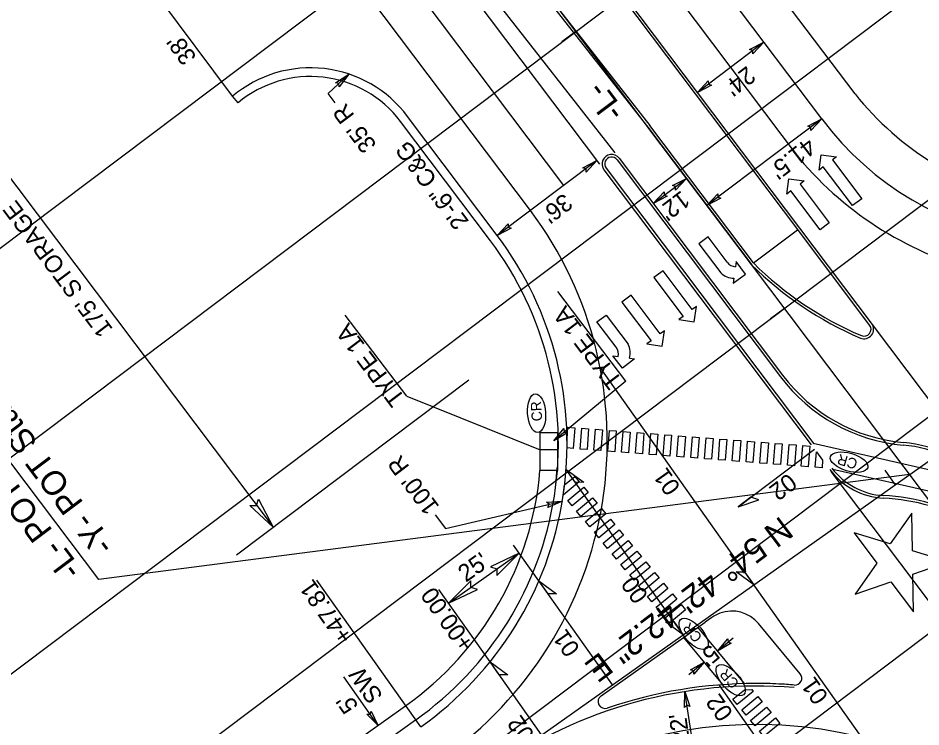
# Model space of a CAD drawing. Extents: x 1262309 to 1264352, y 775189 to 777755.
# Drawn here: x 1263122.7 to 1263383.2, y 776491.3 to 776695.9 of the extents above; entities that cross this region are included whole.
import ezdxf

# ---------------------------------------------------------------- set-up
doc = ezdxf.new("R2010")
doc.units = 0
for name, color, linetype in [('Default', 7, 'Continuous'), ('Old_Level_2', 7, 'Continuous'), ('Prop Conc 1ft 6in Curb and Gutter', 7, 'Continuous'), ('Prop Conc 2ft 6in Curb and Gutter', 7, 'Continuous'), ('Prop Conc 4in Sidewalk', 7, 'Continuous'), ('Prop Conc 5in Monolithic Keyed In Island', 7, 'Continuous'), ('Prop Conc 5in Monolithic Surface Mount Island', 7, 'Continuous'), ('Prop Dimension', 7, 'Continuous'), ('Prop Dimension Text', 7, 'Continuous'), ('Prop EOT', 7, 'Continuous'), ('Prop Horizontal Alignment', 7, 'Continuous'), ('Prop Horizontal Alignment Direction Label', 7, 'Continuous'), ('Prop Horizontal Alignment Station Label', 7, 'Continuous'), ('Prop Horizontal Alignment Tick Large', 7, 'Continuous'), ('Prop Horizontal Alignment Tick Small', 7, 'Continuous'), ('Prop Lane Arrow CELL', 7, 'Continuous'), ('Prop Lane Lines', 7, 'Continuous'), ('Prop Mkg Solid White Crosswalks', 7, 'Continuous'), ('Prop Paved Shoulder', 7, 'Continuous'), ('Prop RDY Traffic Signal CELL', 7, 'Continuous'), ('Prop Superelevation  Arrow CELL', 7, 'Continuous'), ('Prop Superelevation Label', 7, 'Continuous'), ('Prop Terminator CELL', 7, 'Continuous'), ('Scratch_Level_3', 7, 'Continuous')]:
    doc.layers.add(name, color=color, linetype=linetype)

msp = doc.modelspace()

# ---------------------------------------------------------------- linework, layer by layer
at = {"layer": 'Default'}
msp.add_line((1263283.6, 776691.99), (1263283.6, 776691.99), dxfattribs=at)
msp.add_line((1263283.6, 776691.99), (1263283.6, 776691.99), dxfattribs=at)
for centre, major_axis in [((1263272.29, 776581.88), (-0.35, 5.6)), ((1263362.45, 776567.74), (-5.38, 1.6)), ((1263317.6, 776518.17), (-3.75, 4.17)), ((1263328.26, 776504.81), (-3.75, 4.17))]:
    msp.add_ellipse(centre, major_axis=major_axis, ratio=0.462467, dxfattribs=at)
at = {"layer": 'Old_Level_2'}
for p, q in [((1263273.31, 776571.31), (1263273.32, 776576.31)), ((1263273.32, 776576.31), (1263278.32, 776576.3)), ((1263278.32, 776576.3), (1263278.31, 776571.3)), ((1263273.3, 776565.31), (1263273.31, 776571.31)), ((1263278.31, 776571.3), (1263273.31, 776571.31)), ((1263278.31, 776571.3), (1263278.3, 776565.3)), ((1263278.3, 776565.3), (1263273.3, 776565.31))]:
    msp.add_line(p, q, dxfattribs=at)
at = {"layer": 'Prop Conc 1ft 6in Curb and Gutter'}
for p, q in [((1263347.62, 776634.83), (1263140.59, 776909.69)), ((1263123.37, 776896.82), (1263304.93, 776664.85)), ((1263334.84, 776625.2), (1263304.93, 776664.85))]:
    msp.add_line(p, q, dxfattribs=at)
msp.add_arc((1263293.92, 776653.77), 2, 37.0029, 217.0037, dxfattribs=at)
at = {"layer": 'Prop Conc 2ft 6in Curb and Gutter'}
for p, q in [((1263186.18, 776671.42), (1263184.58, 776673.34)), ((1263258.96, 776631.62), (1263233.02, 776666.06)), ((1263218.79, 776480.21), (1263237.4, 776493.38))]:
    msp.add_line(p, q, dxfattribs=at)
for centre, radius, start, end in [((1263207.06, 776646.51), 32.5, 36.9874, 129.9598), ((1263181.08, 776572.96), 97.5, 305.2883, 36.9874)]:
    msp.add_arc(centre, radius, start, end, dxfattribs=at)
at = {"layer": 'Prop Conc 4in Sidewalk'}
for p, q in [((1263352.07, 776573.23), (1263401.96, 776561.79)), ((1263277.85, 776561.08), (1263278.2, 776566.07)), ((1263357.74, 776565.71), (1263408.37, 776554.17)), ((1263332.3, 776503.85), (1263318.84, 776520.08)), ((1263326.06, 776503.55), (1263314.74, 776517.18)), ((1263215.93, 776484.31), (1263234.51, 776497.46))]:
    msp.add_line(p, q, dxfattribs=at)
msp.add_arc((1263181.08, 776572.96), 92.5, 305.2883, 355.251, dxfattribs=at)
at = {"layer": 'Prop Conc 5in Monolithic Keyed In Island'}
for p, q in [((1263295.52, 776654.97), (1263342.67, 776592.37)), ((1263292.32, 776652.57), (1263352.25, 776573)), ((1263334.84, 776625.2), (1263347.59, 776634.81)), ((1263368.37, 776607.28), (1263347.62, 776634.83)), ((1263322.87, 776522.94), (1263320.88, 776521.53)), ((1263290.88, 776500.29), (1263320.88, 776521.53)), ((1263348.34, 776506.7), (1263336.34, 776521.16))]:
    msp.add_line(p, q, dxfattribs=at)
for centre, radius, start, end in [((1263405.23, 776696.15), 99.94, 225.2272, 246.8818), ((1263366.77, 776606.08), 2, 246.8818, 36.9866), ((1263382.61, 776622.45), 50, 216.9874, 264.7486), ((1263374.37, 776532.83), 40, 46.384, 84.7486), ((1263373.47, 776578.07), 20, 216.9874, 266.8533), ((1263368.91, 776495.2), 63, 36.9874, 86.8533), ((1263328.65, 776514.77), 10, 110.1849, 125.2883), ((1263328.65, 776514.77), 10, 39.6905, 110.1849), ((1263346.8, 776505.43), 2, 265.2295, 39.6905), ((1263335.59, 776371.14), 132.75, 90.0327, 108.8618), ((1263335.59, 776371.14), 132.75, 87.1691, 90.0327), ((1263335.59, 776371.14), 132.75, 85.2295, 87.1691), ((1263292.03, 776498.66), 2, 125.2883, 288.8618)]:
    msp.add_arc(centre, radius, start, end, dxfattribs=at)
at = {"layer": 'Prop Conc 5in Monolithic Surface Mount Island'}
msp.add_line((1263292.72, 776655.37), (1263292.72, 776655.37), dxfattribs=at)
at = {"layer": 'Prop Dimension'}
for p, q in [((1263091.05, 776688.64), (1263196.28, 776548.94)), ((1263212.13, 776674.14), (1263218.15, 776679.67)), ((1263214.19, 776671.4), (1263212.13, 776674.14)), ((1263354.56, 776666.75), (1263321.41, 776641.78)), ((1263289.71, 776654.79), (1263260.95, 776633.13)), ((1263234.82, 776586.76), (1263217.1, 776610.16)), ((1263185.76, 776541.02), (1263252.78, 776591.5)), ((1263234.82, 776586.76), (1263273.31, 776571.31)), ((1263246.05, 776548.59), (1263279.72, 776556.52)), ((1263243.04, 776552.58), (1263246.05, 776548.59)), ((1263272.95, 776533.48), (1263265.64, 776543.82)), ((1263246.89, 776527.03), (1263267.3, 776541.47)), ((1263258.86, 776510.12), (1263244.06, 776531.03)), ((1263328.97, 776516.96), (1263324.5, 776513.25)), ((1263320.66, 776510.06), (1263316.18, 776506.34)), ((1263318.43, 776479.93), (1263315.02, 776501.53))]:
    msp.add_line(p, q, dxfattribs=at)
at = {"layer": 'Prop Dimension Text'}
for p, q in [((1263337.8, 776688.92), (1263328.25, 776681.65)), ((1263328.25, 776681.65), (1263318.7, 776674.39)), ((1263305.92, 776642.4), (1263315.51, 776649.62)), ((1263298.01, 776591.1), (1263278.44, 776616.97)), ((1263298.01, 776591.1), (1263277.25, 776573.87)), ((1263238.85, 776491.34), (1263208.89, 776533.66)), ((1263226.53, 776491.81), (1263216.65, 776505.78))]:
    msp.add_line(p, q, dxfattribs=at)
for points in [[(1263333.75, 776686.81), (1263337.8, 776688.92), (1263334.69, 776685.54), (1263334.66, 776686.53)], [(1263322.75, 776676.5), (1263318.7, 776674.39), (1263321.82, 776677.77), (1263321.85, 776676.78)], [(1263285.66, 776652.68), (1263289.71, 776654.79), (1263286.59, 776651.41), (1263286.57, 776652.4)], [(1263265, 776635.24), (1263260.95, 776633.13), (1263264.07, 776636.5), (1263264.1, 776635.52)], [(1263281.18, 776576.18), (1263277.25, 776573.87), (1263280.19, 776577.4), (1263280.26, 776576.42)], [(1263192.1, 776557.06), (1263196.28, 776548.94), (1263189.56, 776555.21), (1263191.53, 776555.25)], [(1263260.85, 776535), (1263267.3, 776541.47), (1263258.99, 776537.55), (1263260.85, 776536.91)], [(1263253.35, 776533.49), (1263246.89, 776527.03), (1263255.21, 776530.95), (1263253.34, 776531.59)]]:
    msp.add_lwpolyline(points, close=True, dxfattribs=at)
at = {"layer": 'Prop EOT'}
for p, q in [((1263354.56, 776666.75), (1263027.28, 777101.26)), ((1263369.15, 776607.49), (1263141.16, 776910.18)), ((1263122.79, 776896.34), (1263304.34, 776664.39)), ((1263184.58, 776673.34), (1263162.01, 776703.54)), ((1263260.95, 776633.13), (1263235.06, 776667.5)), ((1263334.27, 776624.72), (1263304.34, 776664.39)), ((1263304.34, 776664.39), (1263334.27, 776624.72)), ((1263296.12, 776655.42), (1263343.27, 776592.82)), ((1263291.72, 776652.11), (1263351.48, 776572.78))]:
    msp.add_line(p, q, dxfattribs=at)
for centre, radius, start, end in [((1263207.06, 776646.51), 35, 36.8507, 129.9598), ((1263426.45, 776720.9), 90, 216.9873, 305.2883), ((1263293.92, 776653.77), 2.75, 36.9549, 216.9881), ((1263181.08, 776572.96), 100, 305.2883, 36.9874), ((1263405.23, 776696.15), 100.69, 225.2272, 246.8818), ((1263366.77, 776606.08), 2.75, 246.8818, 36.9866), ((1263382.61, 776622.45), 49.25, 216.9874, 264.7486), ((1263374.37, 776532.83), 40.75, 45.4749, 84.7486), ((1263373.47, 776578.07), 20.75, 216.9874, 266.8533), ((1263368.91, 776495.2), 62.25, 36.9874, 86.8533)]:
    msp.add_arc(centre, radius, start, end, dxfattribs=at)
at = {"layer": 'Prop Horizontal Alignment'}
for p, q in [((1263334.24, 776624.75), (1263127.22, 776899.61)), ((1263049.28, 776330.22), (1263743.09, 776821.26)), ((1263830.93, 775965.32), (1263334.24, 776624.75))]:
    msp.add_line(p, q, dxfattribs=at)
at = {"layer": 'Prop Horizontal Alignment Direction Label'}
msp.add_line((1263145.97, 776533.85), (1263065.13, 776641.04), dxfattribs=at)
msp.add_lwpolyline([(1263379.86, 776564.19), (1263145.97, 776533.85)], dxfattribs=at)
at = {"layer": 'Prop Horizontal Alignment Tick Large'}
msp.add_line((1263294.15, 776503.53), (1263289.53, 776510.06), dxfattribs=at)
at = {"layer": 'Prop Horizontal Alignment Tick Small'}
for p, q in [((1263283.6, 776691.99), (1263279.6, 776688.98)), ((1263343.76, 776612.11), (1263339.77, 776609.1)), ((1263375.78, 776561.3), (1263372.89, 776565.38)), ((1263294.15, 776503.53), (1263291.26, 776507.61))]:
    msp.add_line(p, q, dxfattribs=at)
at = {"layer": 'Prop Lane Arrow CELL'}
for p, q in [((1263353.82, 776652.03), (1263354.4, 776656.41)), ((1263354.4, 776656.41), (1263358.85, 776655.82)), ((1263358.85, 776655.82), (1263357.65, 776654.92)), ((1263355.01, 776652.93), (1263353.82, 776652.03)), ((1263363.44, 776641.75), (1263355.01, 776652.93)), ((1263357.65, 776654.92), (1263366.07, 776643.73)), ((1263344.47, 776645.09), (1263345.05, 776649.47)), ((1263345.05, 776649.47), (1263349.5, 776648.88)), ((1263349.5, 776648.88), (1263348.3, 776647.98)), ((1263348.3, 776647.98), (1263356.73, 776636.79)), ((1263345.67, 776645.99), (1263344.47, 776645.09)), ((1263354.09, 776634.81), (1263345.67, 776645.99)), ((1263366.07, 776643.73), (1263363.44, 776641.75)), ((1263356.73, 776636.79), (1263354.09, 776634.81)), ((1263321.77, 776632.75), (1263319.13, 776630.76)), ((1263327.27, 776625.44), (1263321.77, 776632.75)), ((1263319.13, 776630.76), (1263325.48, 776622.33)), ((1263329.9, 776625.6), (1263329.7, 776624.13)), ((1263332.57, 776621.98), (1263329.9, 776625.6)), ((1263308.79, 776622.97), (1263306.15, 776620.98)), ((1263317.21, 776611.79), (1263308.79, 776622.97)), ((1263329.02, 776619.37), (1263332.57, 776621.98)), ((1263306.15, 776620.98), (1263314.57, 776609.8)), ((1263329.23, 776620.84), (1263329.02, 776619.37)), ((1263299.54, 776615.9), (1263296.9, 776613.92)), ((1263296.9, 776613.92), (1263305.32, 776602.73)), ((1263307.96, 776604.72), (1263299.54, 776615.9)), ((1263318.41, 776612.69), (1263317.21, 776611.79)), ((1263317.75, 776608.25), (1263318.41, 776612.69)), ((1263289.7, 776608.2), (1263292.34, 776610.18)), ((1263292.34, 776610.18), (1263298.69, 776601.76)), ((1263314.57, 776609.8), (1263313.37, 776608.9)), ((1263313.37, 776608.9), (1263317.75, 776608.25)), ((1263295.21, 776600.89), (1263289.7, 776608.2)), ((1263309.16, 776605.62), (1263307.96, 776604.72)), ((1263308.5, 776601.18), (1263309.16, 776605.62)), ((1263305.32, 776602.73), (1263304.12, 776601.83)), ((1263304.12, 776601.83), (1263308.5, 776601.18)), ((1263297.07, 776594.84), (1263294.32, 776598.41)), ((1263294.32, 776598.41), (1263295.79, 776598.2)), ((1263300.55, 776597.53), (1263297.07, 776594.84)), ((1263299.08, 776597.74), (1263300.55, 776597.53))]:
    msp.add_line(p, q, dxfattribs=at)
for centre, radius, start, end in [((1263329.88, 776627.39), 3.27, 216.9874, 266.6456), ((1263329.14, 776626.08), 5.25, 225.6635, 270.9752), ((1263292.61, 776598.92), 3.27, 347.3292, 36.9874), ((1263294.07, 776599.28), 5.25, 342.9996, 28.3113)]:
    msp.add_arc(centre, radius, start, end, dxfattribs=at)
at = {"layer": 'Prop Lane Lines'}
for p, q in [((1263348.11, 776655.37), (1262839.39, 777330.78)), ((1263290.52, 776653.71), (1263113.2, 776889.12)), ((1263113.42, 776888.84), (1263294.89, 776656.99)), ((1263280.15, 776647.53), (1263120.31, 776859.74)), ((1263270.54, 776640.35), (1263188.37, 776749.45)), ((1263406.92, 776557.35), (1263369.15, 776607.49)), ((1263392.17, 776518.75), (1263357.3, 776565.05))]:
    msp.add_line(p, q, dxfattribs=at)
for centre, radius, start, end in [((1263424.65, 776719.73), 100, 220.0607, 256.4057), ((1263181.18, 776573.65), 111.5, 305.0388, 36.738), ((1263335.59, 776371.14), 132, 85.2295, 125.2883), ((1263336.03, 776369.27), 122.79, 37.8117, 124.9498)]:
    msp.add_arc(centre, radius, start, end, dxfattribs=at)
at = {"layer": 'Prop Mkg Solid White Crosswalks'}
for points in [[(1263282.86, 776571.69), (1263281.07, 776571.83), (1263281.07, 776574.45), (1263281.33, 776577.83), (1263283.32, 776577.67)], [(1263285.32, 776577.52), (1263287.31, 776577.36), (1263286.84, 776571.38), (1263284.85, 776571.53)], [(1263289.31, 776577.21), (1263291.3, 776577.05), (1263290.83, 776571.07), (1263288.84, 776571.22)], [(1263293.29, 776576.89), (1263295.29, 776576.74), (1263294.82, 776570.76), (1263292.83, 776570.91)], [(1263297.28, 776576.58), (1263299.27, 776576.43), (1263298.81, 776570.45), (1263296.81, 776570.6)], [(1263301.27, 776576.27), (1263303.26, 776576.12), (1263302.8, 776570.14), (1263300.8, 776570.29)], [(1263305.26, 776575.96), (1263307.25, 776575.81), (1263306.78, 776569.82), (1263304.79, 776569.98)], [(1263309.24, 776575.65), (1263311.24, 776575.5), (1263310.77, 776569.51), (1263308.78, 776569.67)], [(1263313.23, 776575.34), (1263315.23, 776575.18), (1263314.76, 776569.2), (1263312.77, 776569.36)], [(1263317.22, 776575.03), (1263319.21, 776574.87), (1263318.75, 776568.89), (1263316.75, 776569.05)], [(1263321.21, 776574.72), (1263323.2, 776574.56), (1263322.74, 776568.58), (1263320.74, 776568.74)], [(1263325.2, 776574.41), (1263327.19, 776574.25), (1263326.72, 776568.27), (1263324.73, 776568.43)], [(1263329.18, 776574.1), (1263331.18, 776573.94), (1263330.71, 776567.96), (1263328.72, 776568.11)], [(1263333.17, 776573.79), (1263335.17, 776573.63), (1263334.7, 776567.65), (1263332.71, 776567.8)], [(1263337.16, 776573.47), (1263339.15, 776573.32), (1263338.69, 776567.34), (1263336.69, 776567.49)], [(1263341.15, 776573.16), (1263343.14, 776573.01), (1263342.68, 776567.03), (1263340.68, 776567.18)], [(1263345.14, 776572.85), (1263347.13, 776572.7), (1263346.66, 776566.72), (1263344.67, 776566.87)], [(1263349.12, 776572.54), (1263351.12, 776572.39), (1263350.65, 776566.4), (1263348.66, 776566.56)], [(1263354.81, 776568.35), (1263354.64, 776566.09), (1263352.65, 776566.25), (1263353, 776570.76)], [(1263283.34, 776563.62), (1263284.61, 776562.08), (1263280, 776558.25), (1263279.99, 776558.26), (1263280.38, 776561.17)], [(1263285.89, 776560.54), (1263287.17, 776559), (1263282.55, 776555.17), (1263281.27, 776556.71)], [(1263288.44, 776557.47), (1263289.72, 776555.93), (1263285.1, 776552.09), (1263283.83, 776553.63)], [(1263291.01, 776554.4), (1263292.29, 776552.86), (1263287.67, 776549.03), (1263286.4, 776550.57)], [(1263293.57, 776551.32), (1263294.84, 776549.78), (1263290.23, 776545.95), (1263288.95, 776547.49)], [(1263296.12, 776548.24), (1263297.4, 776546.7), (1263292.78, 776542.87), (1263291.5, 776544.41)], [(1263298.68, 776545.16), (1263299.95, 776543.62), (1263295.33, 776539.79), (1263294.06, 776541.33)], [(1263301.23, 776542.08), (1263302.51, 776540.55), (1263297.89, 776536.71), (1263296.61, 776538.25)], [(1263303.78, 776539.01), (1263305.06, 776537.47), (1263300.44, 776533.64), (1263299.17, 776535.18)], [(1263306.34, 776535.93), (1263307.61, 776534.39), (1263303, 776530.56), (1263301.72, 776532.1)], [(1263308.89, 776532.85), (1263310.17, 776531.31), (1263305.55, 776527.48), (1263304.27, 776529.02)], [(1263311.45, 776529.77), (1263312.72, 776528.23), (1263308.1, 776524.4), (1263306.83, 776525.94)], [(1263314, 776526.69), (1263315.28, 776525.15), (1263310.66, 776521.32), (1263309.38, 776522.86)], [(1263332.25, 776502.09), (1263334.38, 776502.13), (1263334.81, 776501.61), (1263330.19, 776497.78), (1263328.92, 776499.32)], [(1263336.09, 776500.08), (1263337.36, 776498.54), (1263332.75, 776494.71), (1263331.47, 776496.24)], [(1263338.64, 776497), (1263339.92, 776495.46), (1263335.3, 776491.63), (1263334.02, 776493.17)], [(1263341.2, 776493.92), (1263342.47, 776492.38), (1263337.85, 776488.55), (1263336.58, 776490.09)]]:
    msp.add_lwpolyline(points, close=True, dxfattribs=at)
at = {"layer": 'Prop Paved Shoulder'}
msp.add_line((1263364.15, 776673.97), (1263021.01, 777129.53), dxfattribs=at)
msp.add_arc((1263434.28, 776730.38), 90, 218.8085, 238.3878, dxfattribs=at)
at = {"layer": 'Prop RDY Traffic Signal CELL'}
msp.add_lwpolyline([(1263374.48, 776533.24), (1263381.03, 776524.55), (1263380.84, 776535.43), (1263391.15, 776538.98), (1263380.72, 776542.17), (1263380.53, 776553.06), (1263374.28, 776544.14), (1263363.87, 776547.32), (1263370.42, 776538.63), (1263364.17, 776529.69), (1263374.48, 776533.24)], dxfattribs=at)
at = {"layer": 'Prop Superelevation  Arrow CELL'}
for p, q in [((1263376.97, 776473.07), (1263290.6, 776595.09)), ((1263330.4, 776554.87), (1263352.44, 776571.51)), ((1263314.58, 776517.94), (1263280.81, 776565.66)), ((1263294.15, 776503.53), (1263272.95, 776533.48)), ((1263273.75, 776489.09), (1263258.86, 776510.12)), ((1263324.83, 776503.46), (1263340.71, 776481.03))]:
    msp.add_line(p, q, dxfattribs=at)
for points in [[(1263280.81, 776565.66), (1263285.91, 776561.92), (1263283.48, 776561.88)], [(1263330.4, 776554.87), (1263336.39, 776556.89), (1263334.09, 776557.65)], [(1263334.95, 776532.37), (1263329.85, 776536.11), (1263332.27, 776536.14)], [(1263272.95, 776533.48), (1263278.05, 776529.74), (1263275.62, 776529.71)], [(1263314.58, 776517.94), (1263309.48, 776521.69), (1263311.91, 776521.72)], [(1263258.86, 776510.12), (1263263.96, 776506.38), (1263261.53, 776506.34)]]:
    msp.add_lwpolyline(points, close=True, dxfattribs=at)
at = {"layer": 'Prop Terminator CELL'}
for points in [[(1263214.31, 776677.2), (1263218.15, 776679.67), (1263215.36, 776676.02), (1263215.24, 776677)], [(1263350.5, 776664.66), (1263354.56, 776666.75), (1263351.43, 776663.39), (1263351.41, 776664.37)], [(1263311.45, 776647.53), (1263315.51, 776649.62), (1263312.38, 776646.26), (1263312.35, 776647.25)], [(1263309.98, 776644.49), (1263305.92, 776642.4), (1263309.06, 776645.76), (1263309.08, 776644.78)], [(1263325.47, 776643.87), (1263321.41, 776641.78), (1263324.55, 776645.14), (1263324.57, 776644.16)], [(1263275.16, 776556.24), (1263279.72, 776556.52), (1263275.49, 776554.7), (1263275.87, 776555.61)], [(1263328.46, 776515.53), (1263324.5, 776513.25), (1263327.47, 776516.76), (1263327.54, 776515.77)], [(1263316.7, 776507.78), (1263320.66, 776510.06), (1263317.68, 776506.55), (1263317.62, 776507.54)], [(1263314.95, 776496.96), (1263315.02, 776501.53), (1263316.51, 776497.19), (1263315.63, 776497.63)], [(1263224.57, 776495.93), (1263226.53, 776491.81), (1263223.27, 776495.04), (1263224.25, 776495.04)]]:
    msp.add_lwpolyline(points, close=True, dxfattribs=at)
at = {"layer": 'Scratch_Level_3'}
for p, q in [((1263055.58, 776582.84), (1263550.68, 776955.75)), ((1263085.66, 776542.9), (1263580.76, 776915.82)), ((1263115.74, 776502.96), (1263610.84, 776875.88)), ((1263145.82, 776463.02), (1263640.93, 776835.94)), ((1263175.91, 776423.09), (1263671.01, 776796)), ((1263205.99, 776383.15), (1263701.09, 776756.06))]:
    msp.add_line(p, q, dxfattribs=at)

# ---------------------------------------------------------------- texts
at = {"layer": 'Default'}
for rotation, p in [(93.5483, (1263273.92, 776579.62)), (163.4716, (1263365.13, 776568.49)), (131.9108, (1263320.27, 776517.4)), (131.9108, (1263330.93, 776504.05))]:
    msp.add_text('CR', height=3, rotation=rotation, dxfattribs=at).set_placement(p)
at = {"layer": 'Prop Dimension'}
for s, rotation, p in [("38'", 125.4267, (1263174.38, 776684.64)), ("35' R", 127.0213, (1263226.33, 776659.33)), ('TYPE 1A', 127.0213, (1263297.25, 776591.27)), ('TYPE 1A', 127.0213, (1263234.59, 776586.2)), ("100' R", 127.0213, (1263244.43, 776554.93)), ("5'", 219.985, (1263322.41, 776515.44)), ("22'", 98.2283, (1263316.58, 776486.88))]:
    msp.add_text(s, height=5, rotation=rotation, dxfattribs=at).set_placement(p)
at = {"layer": 'Prop Dimension Text'}
for s, rotation, p in [("24'", 217.2584, (1263332.99, 776682.24)), ('2\'-6" C&G', 126.9874, (1263252.94, 776637.23)), ("41.5'", 217.2584, (1263350.45, 776661.62)), ("12'", 217.2584, (1263314.08, 776646.32)), ("175' STORAGE", 126.9874, (1263150.25, 776606.14)), ("36'", 217.2584, (1263280.19, 776645.54)), ("25'", 35.2883, (1263251.89, 776532.92)), ('+47.81', 125.2883, (1263219.56, 776517.47)), ('+00.00', 125.2883, (1263254.56, 776515.33)), ('SW', 125.2883, (1263228.17, 776500.36)), ("5'", 125.2883, (1263221.09, 776497.4))]:
    msp.add_text(s, height=5, rotation=rotation, dxfattribs=at).set_placement(p)
at = {"layer": 'Prop Horizontal Alignment Direction Label'}
for s, rotation, p in [('-L- POT Sta. 675+40.00 =', 126.9874, (1263141.32, 776536.76)), ('-Y- POT Sta. 12+05.00', 126.9874, (1263150.83, 776543.92)), ('N 54%%d 42\' 42.2" E', 217.0213, (1263342.71, 776552.38))]:
    msp.add_text(s, height=7, rotation=rotation, dxfattribs=at).set_placement(p)
at = {"layer": 'Prop Horizontal Alignment Station Label'}
msp.add_text('-L-', height=7, rotation=126.9874, dxfattribs=at).set_placement((1263298.02, 776668.94))
at = {"layer": 'Prop Superelevation Label'}
for s, rotation, p in [('01', 125.2883, (1263314.01, 776560.49)), ('02', 217.0553, (1263344.91, 776564.78)), ('00', 125.2883, (1263304.73, 776529.27)), ('01', 125.2883, (1263285, 776513.88)), ('01', 125.2883, (1263356.67, 776500.14)), ('02', 125.2883, (1263329.19, 776495.29)), ('02', 125.2883, (1263271.9, 776489.11))]:
    msp.add_text(s, height=5, rotation=rotation, dxfattribs=at).set_placement(p)

doc.saveas('drawing.dxf')
